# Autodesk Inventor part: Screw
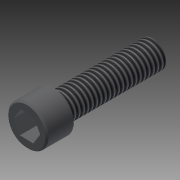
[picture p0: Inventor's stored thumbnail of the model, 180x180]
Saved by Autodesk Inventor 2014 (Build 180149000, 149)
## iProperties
Created: 2006-07
Part Number: Screw
Material: system_material_0
Description: SCREW, CAP, 1/4-20 X 3/8
Document SubType Name: Modeling
Designer: Z.MCGILL
Engineer: SAP
Manufacturer: Standard
Standards Organization: Custom
Mass: 26.2447 g
Surface Area: 18.9522 cm^2
Volume: 3.34682 cm^3
Density: 7.84168 g/cm^3
Appearance: system_RenderingStyle_0
NetWeight: 0.005
WeightUOM: KG
ModelCode: Comp
Author: Z.MCGILL
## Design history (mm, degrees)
node "SHCS"
body "Solid1"
tag "TaggingFeature2"
feature "DerivedBody::SHCS"
other parameters: "Thread_Length" = 41.275, "Head_Chamfer" = 0.635, "Thread_Chamfer" = 0.2286, "Thread_Diameter" = 11.1125, "Head_Diameter" = 16.66748, "Head_Length" = 11.1125, "Hex_Head_Width" = 9.525, "Hex_Head_Depth" = 9.525, "d23" = 0, "d24" = 0
